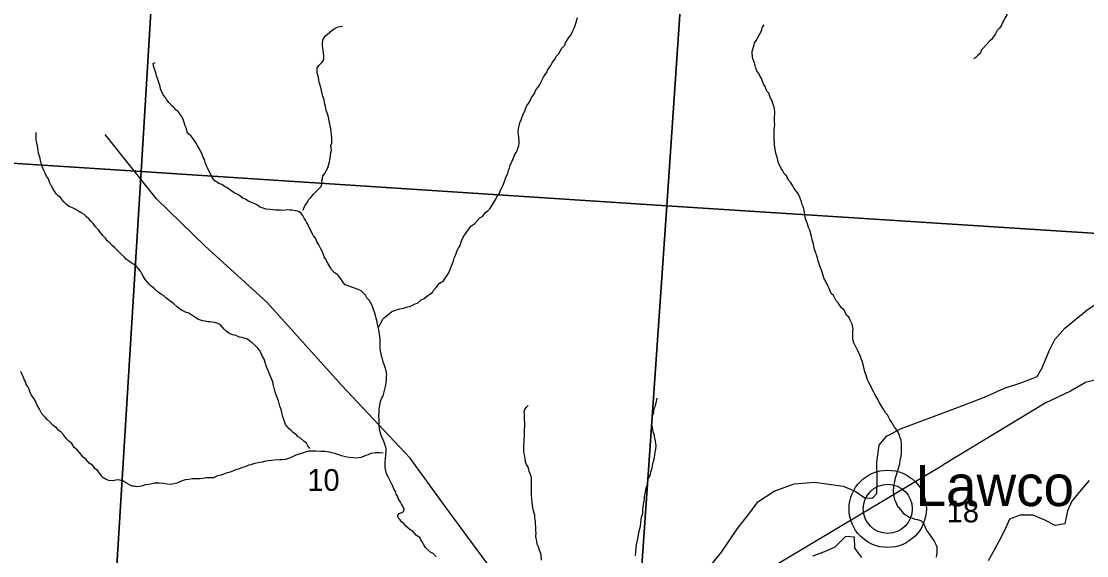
# Model space of a CAD drawing. Extents: x 0 to 44, y -23.8 to 22.
# Drawn here: x 5.27 to 7.321, y 17.815 to 18.843 of the extents above; entities that cross this region are included whole.
import ezdxf

# ---------------------------------------------------------------- set-up
doc = ezdxf.new("R2010")
doc.units = 0
for name, color, linetype in [('GM_X_County_Road', 7, 'Continuous'), ('GM_X_Minor_River', 7, 'Continuous'), ('GM_X_Rail_Line', 7, 'Continuous'), ('GM_X_Section', 7, 'Continuous'), ('GM_X_Section_Text', 7, 'Continuous'), ('GM_X_Township_Road', 7, 'Continuous'), ('GM_X_Unincorporated', 7, 'Continuous'), ('GM_X_Unincorporated_Location', 7, 'Continuous'), ('GM_X_Unincorporated_Text', 7, 'Continuous')]:
    doc.layers.add(name, color=color, linetype=linetype)

msp = doc.modelspace()

# ---------------------------------------------------------------- linework, layer by layer
at = {"layer": 'GM_X_County_Road'}
for points in [[(6.9605, 18.0572), (6.9631, 18.0586), (7.0676, 18.0977), (7.1245, 18.1197), (7.1631, 18.1368), (7.1965, 18.1482), (7.2162, 18.1554), (7.226, 18.1596), (7.2355, 18.1759), (7.2488, 18.2089), (7.2601, 18.2305), (7.2791, 18.2525), (7.3219, 18.2874), (7.3518, 18.3079), (7.3662, 18.3212), (7.3901, 18.3277), (7.4398, 18.3193), (7.4838, 18.3016), (7.5032, 18.2938)], [(6.5891, 17.785), (6.6186, 17.8214), (6.6489, 17.8669), (6.6728, 17.8969), (6.6883, 17.9182), (6.7198, 17.939), (6.7584, 17.9527), (6.7975, 17.9565), (6.8524, 17.9482), (6.8755, 17.9387), (6.8941, 17.9258), (6.9093, 17.9254), (6.9172, 17.9341), (6.918, 17.9614), (6.9172, 17.9948), (6.9218, 18.0275), (6.9362, 18.0445), (6.9474, 18.0504), (6.9605, 18.0572)]]:
    msp.add_lwpolyline(points, dxfattribs=at)
at = {"layer": 'GM_X_Minor_River'}
for points in [[(6.3108, 18.7915), (6.3169, 18.7971), (6.3181, 18.8017), (6.3243, 18.8115), (6.3285, 18.816), (6.3324, 18.8247), (6.3347, 18.8296), (6.3367, 18.8349), (6.3382, 18.839), (6.3414, 18.85)], [(7.1697, 18.8616), (7.1674, 18.8552), (7.1635, 18.8491), (7.1616, 18.8453), (7.1569, 18.8344), (7.1534, 18.8299), (7.1492, 18.825), (7.1457, 18.8186), (7.1388, 18.8088), (7.1334, 18.8039), (7.1288, 18.7983), (7.1226, 18.7919), (7.1184, 18.7874), (7.1172, 18.7813), (7.1118, 18.7768), (7.108, 18.7734), (7.1042, 18.7705)], [(5.8128, 18.4795), (5.8144, 18.4836), (5.8163, 18.4878), (5.8198, 18.4927), (5.8241, 18.4998), (5.8279, 18.5036), (5.8337, 18.5107), (5.8379, 18.5156), (5.8471, 18.5246), (5.8487, 18.5288), (5.8495, 18.5326), (5.8488, 18.5364), (5.85, 18.5401), (5.8512, 18.5458), (5.8546, 18.5503), (5.857, 18.5553), (5.8604, 18.5609), (5.8636, 18.5723), (5.8644, 18.5764), (5.8656, 18.5848), (5.8661, 18.5905), (5.8673, 18.5943), (5.8666, 18.6041), (5.8682, 18.6087), (5.8682, 18.6132), (5.8679, 18.6174), (5.8676, 18.6243), (5.8669, 18.63), (5.8662, 18.6361), (5.8648, 18.6418), (5.8644, 18.6456), (5.863, 18.6502), (5.8623, 18.6555), (5.8612, 18.6612), (5.8597, 18.665), (5.8575, 18.6711), (5.8568, 18.6749), (5.8561, 18.6799), (5.8546, 18.6837), (5.8532, 18.6913), (5.851, 18.699), (5.8492, 18.7062), (5.8474, 18.7127), (5.8463, 18.7173), (5.8452, 18.7218), (5.8441, 18.7256), (5.8434, 18.7298), (5.8423, 18.7352), (5.8412, 18.739), (5.8402, 18.7439), (5.8398, 18.7477), (5.8399, 18.7531), (5.8434, 18.7576), (5.8487, 18.7636), (5.8522, 18.7677), (5.8526, 18.7719), (5.8527, 18.7757), (5.8524, 18.7821), (5.8513, 18.7871), (5.8506, 18.7913), (5.8503, 18.7962), (5.8503, 18.8004), (5.8511, 18.8069), (5.8527, 18.811), (5.8558, 18.8148), (5.8596, 18.8182), (5.868, 18.8249), (5.8745, 18.8297), (5.8806, 18.8323), (5.8844, 18.833), (5.889, 18.8337)], [(6.8237, 18.3329), (6.8193, 18.3424), (6.8159, 18.3474), (6.8119, 18.36), (6.8071, 18.3745), (6.8042, 18.3814), (6.8038, 18.3852), (6.8013, 18.3939), (6.799, 18.3989), (6.7969, 18.4065), (6.7954, 18.4138), (6.7925, 18.4252), (6.7914, 18.429), (6.7885, 18.4408), (6.7859, 18.4462), (6.7834, 18.455), (6.7815, 18.4592), (6.7797, 18.4656), (6.7783, 18.4752), (6.7772, 18.4797), (6.7761, 18.4847), (6.7739, 18.4904), (6.7725, 18.4958), (6.7695, 18.5026), (6.7666, 18.5106), (6.7621, 18.516), (6.7583, 18.521), (6.7558, 18.5264), (6.7513, 18.5336), (6.7472, 18.5375), (6.7435, 18.5455), (6.7397, 18.549), (6.7364, 18.5555), (6.7334, 18.5597), (6.7308, 18.5654), (6.7282, 18.57), (6.7253, 18.5818), (6.7234, 18.5868), (6.7213, 18.6001), (6.7202, 18.6058), (6.72, 18.6195), (6.7197, 18.6252), (6.7198, 18.6332), (6.7203, 18.6393), (6.7207, 18.6442), (6.7204, 18.6492), (6.7204, 18.653), (6.7205, 18.6583), (6.7209, 18.6651), (6.721, 18.6693), (6.7196, 18.678), (6.7181, 18.6826), (6.7155, 18.6914), (6.7129, 18.6952), (6.7092, 18.7048), (6.7059, 18.7086), (6.7022, 18.7174), (6.6992, 18.722), (6.6955, 18.7327), (6.6929, 18.7365), (6.69, 18.7423), (6.6866, 18.7476), (6.6844, 18.753), (6.6818, 18.7629), (6.6789, 18.7709), (6.6782, 18.7755), (6.6775, 18.7808), (6.6772, 18.785), (6.6791, 18.7918), (6.6811, 18.7971), (6.6819, 18.8016), (6.685, 18.8062), (6.6881, 18.8118), (6.692, 18.8186), (6.6947, 18.8235), (6.6974, 18.8315), (6.7005, 18.836)], [(5.959, 18.2549), (5.9609, 18.2591), (5.9632, 18.2636), (5.9656, 18.2693), (5.9694, 18.2727), (5.9752, 18.2775), (5.979, 18.2809), (5.9836, 18.2846), (5.9874, 18.2861), (5.9946, 18.2883), (5.9988, 18.2898), (6.0068, 18.2912), (6.0114, 18.293), (6.0175, 18.2941), (6.0224, 18.2963), (6.0289, 18.2993), (6.0331, 18.3004), (6.0404, 18.3067), (6.0461, 18.3093), (6.0534, 18.3161), (6.0576, 18.3179), (6.0625, 18.3224), (6.0645, 18.3262), (6.0691, 18.3307), (6.0756, 18.3389), (6.0829, 18.3438), (6.0898, 18.3532), (6.0941, 18.36), (6.0976, 18.3691), (6.1004, 18.377), (6.1023, 18.3819), (6.1039, 18.3872), (6.1058, 18.391), (6.1074, 18.3963), (6.109, 18.4005), (6.1129, 18.4076), (6.1152, 18.4118), (6.1167, 18.4167), (6.1176, 18.4205), (6.1222, 18.4303), (6.1257, 18.4341), (6.1284, 18.4378), (6.1322, 18.4431), (6.1361, 18.4487), (6.1437, 18.454), (6.153, 18.4645), (6.1587, 18.4678), (6.1641, 18.475), (6.1687, 18.4783), (6.1737, 18.484), (6.1791, 18.4923), (6.1826, 18.4987), (6.1872, 18.5074), (6.1903, 18.5111), (6.1934, 18.5194), (6.1958, 18.5236), (6.1989, 18.5296), (6.2012, 18.5364), (6.2032, 18.5429), (6.2055, 18.5478), (6.2075, 18.5527), (6.2083, 18.5565), (6.2102, 18.5603), (6.2114, 18.5652), (6.2141, 18.5712), (6.2165, 18.5769), (6.2196, 18.5852), (6.2231, 18.5905), (6.225, 18.5943), (6.2262, 18.5984), (6.2282, 18.6037), (6.229, 18.6079), (6.229, 18.6121), (6.2284, 18.6197), (6.2273, 18.6258), (6.2269, 18.6296), (6.2274, 18.6368), (6.2302, 18.6478), (6.2329, 18.6534), (6.2365, 18.664), (6.2392, 18.6689), (6.2431, 18.6795), (6.2469, 18.6848), (6.2497, 18.6901), (6.2528, 18.6965), (6.2582, 18.704), (6.2609, 18.7108), (6.2655, 18.7161), (6.2678, 18.7203), (6.2729, 18.7301), (6.2756, 18.7357), (6.2787, 18.7406), (6.2818, 18.7444), (6.2833, 18.7486), (6.2868, 18.7531), (6.2895, 18.7576), (6.293, 18.7644), (6.2968, 18.7685), (6.3007, 18.7757), (6.3046, 18.7794), (6.3108, 18.7915)], [(5.8391, 18.4191), (5.8369, 18.4256), (5.8328, 18.4302), (5.8313, 18.434), (5.8287, 18.4382), (5.8264, 18.4428), (5.8238, 18.4474), (5.8224, 18.4516), (5.8201, 18.4554), (5.8175, 18.4604), (5.8149, 18.4642), (5.8127, 18.4692), (5.8093, 18.473), (5.8056, 18.4761), (5.8018, 18.4777), (5.7976, 18.4785), (5.7916, 18.4793), (5.7874, 18.4794), (5.781, 18.4799), (5.7753, 18.4792), (5.7696, 18.4796), (5.7654, 18.4797), (5.7597, 18.4797), (5.7495, 18.4806), (5.7415, 18.4815), (5.734, 18.4843), (5.7298, 18.4854), (5.7253, 18.4889), (5.72, 18.492), (5.7136, 18.4944), (5.7064, 18.4975), (5.7019, 18.5006), (5.6978, 18.5022), (5.6887, 18.5091), (5.6801, 18.5131), (5.6755, 18.5162), (5.6658, 18.5231), (5.6616, 18.5251), (5.6563, 18.5286), (5.6518, 18.5301), (5.6469, 18.5332), (5.6431, 18.5359), (5.6379, 18.5425), (5.6357, 18.5463), (5.6342, 18.5505), (5.6312, 18.5555), (5.6294, 18.5597), (5.6272, 18.5646), (5.6253, 18.5692), (5.6228, 18.5769), (5.6205, 18.5811), (5.619, 18.5849), (5.618, 18.5887), (5.6153, 18.5929), (5.6135, 18.5975), (5.6098, 18.6036), (5.6068, 18.6082), (5.6035, 18.6143), (5.5971, 18.6216), (5.593, 18.6259), (5.59, 18.6297), (5.5889, 18.6335), (5.5878, 18.6377), (5.5859, 18.6419), (5.5841, 18.6484), (5.5827, 18.6522), (5.5812, 18.656), (5.5789, 18.6602), (5.5748, 18.6652), (5.5722, 18.6694), (5.5685, 18.6718), (5.5643, 18.6768), (5.5606, 18.6795), (5.5546, 18.6868), (5.5497, 18.6922), (5.5479, 18.696), (5.5438, 18.7013), (5.5408, 18.7075), (5.5386, 18.7128), (5.5375, 18.7174), (5.5353, 18.725), (5.5324, 18.7326), (5.5309, 18.738), (5.5295, 18.7437), (5.5284, 18.7479), (5.5258, 18.7548), (5.5243, 18.7616), (5.5282, 18.7635)], [(5.3618, 18.4867), (5.3566, 18.491), (5.3517, 18.4963), (5.3457, 18.5036), (5.3416, 18.5071), (5.3378, 18.511), (5.3341, 18.5163), (5.3311, 18.5209), (5.3285, 18.5255), (5.3248, 18.5335), (5.3226, 18.5396), (5.3189, 18.545), (5.3167, 18.5492), (5.3141, 18.5557), (5.3108, 18.5637), (5.3093, 18.5679), (5.3071, 18.5744), (5.3068, 18.5797), (5.3057, 18.5836), (5.3038, 18.5893), (5.3028, 18.5946), (5.3024, 18.5996), (5.3017, 18.6041), (5.3006, 18.6079), (5.2992, 18.6152), (5.2989, 18.6201), (5.299, 18.6289)], [(5.8258, 18.0211), (5.822, 18.0264), (5.8194, 18.0314), (5.8142, 18.0353), (5.8078, 18.0407), (5.8033, 18.0434), (5.7995, 18.0476), (5.7942, 18.0511), (5.7897, 18.0557), (5.7856, 18.0592), (5.7792, 18.0673), (5.7763, 18.0749), (5.7737, 18.0821), (5.7705, 18.0962), (5.7679, 18.1024), (5.7654, 18.1126), (5.7628, 18.1188), (5.7595, 18.1283), (5.7576, 18.1348), (5.7558, 18.142), (5.7548, 18.1493), (5.7529, 18.1535), (5.7511, 18.1584), (5.7489, 18.163), (5.7459, 18.171), (5.7426, 18.1783), (5.7382, 18.1928), (5.7334, 18.2004), (5.7297, 18.2096), (5.7252, 18.2146), (5.7211, 18.2188), (5.7143, 18.2246), (5.7102, 18.2277), (5.706, 18.2312), (5.6992, 18.2332), (5.6951, 18.2344), (5.6905, 18.2352), (5.6818, 18.2387), (5.6773, 18.2399), (5.6697, 18.2427), (5.6648, 18.2469), (5.6611, 18.2504), (5.654, 18.2588), (5.6487, 18.2615), (5.6423, 18.2632), (5.6377, 18.264), (5.6332, 18.2644), (5.6294, 18.2648), (5.6241, 18.2657), (5.6192, 18.2665), (5.6154, 18.2681), (5.6116, 18.2689), (5.6067, 18.2723), (5.5984, 18.2778), (5.5928, 18.2813), (5.5864, 18.2832), (5.5803, 18.2867), (5.5747, 18.2895), (5.5709, 18.2926), (5.5638, 18.2991), (5.5563, 18.3049), (5.5487, 18.3107), (5.5442, 18.3153), (5.5386, 18.3188), (5.5337, 18.3215), (5.5262, 18.3288), (5.5202, 18.3331), (5.5164, 18.3369), (5.5134, 18.3412), (5.5086, 18.3462), (5.5048, 18.3523), (5.5015, 18.3584), (5.4996, 18.3622), (5.4959, 18.3668), (5.4914, 18.3715), (5.4876, 18.3749), (5.482, 18.378), (5.4767, 18.3823), (5.473, 18.3846), (5.4685, 18.3896), (5.4625, 18.395), (5.4542, 18.4035), (5.4505, 18.4069), (5.4452, 18.4116), (5.4396, 18.4181), (5.4358, 18.4204), (5.4325, 18.4254), (5.4272, 18.4308), (5.4216, 18.4377), (5.419, 18.4419), (5.4134, 18.4477), (5.4093, 18.4531), (5.4044, 18.4584), (5.4003, 18.463), (5.3961, 18.4665), (5.3916, 18.4715), (5.3871, 18.4735), (5.3792, 18.4781), (5.3754, 18.4805), (5.3675, 18.4844), (5.3618, 18.4867)], [(5.9957, 17.8874), (5.995, 17.892), (5.9981, 17.8962), (6.003, 17.898), (6.0068, 17.9006), (6.0073, 17.9044), (6.0054, 17.909), (6.0024, 17.9136), (5.9995, 17.9193), (5.9961, 17.9247), (5.9947, 17.9293), (5.992, 17.9331), (5.9906, 17.938), (5.9876, 17.9434), (5.9858, 17.9484), (5.9828, 17.9533), (5.9813, 17.9575), (5.9783, 17.9625), (5.9769, 17.9667), (5.9739, 17.9709), (5.9728, 17.9747), (5.971, 17.9843), (5.9711, 17.9953), (5.9716, 18.0006), (5.9721, 18.0097), (5.9725, 18.0143), (5.9726, 18.0207), (5.9715, 18.0249), (5.9697, 18.0314), (5.9671, 18.0379), (5.9637, 18.0448), (5.9623, 18.0486), (5.9604, 18.0555), (5.9601, 18.06), (5.9594, 18.0653), (5.9591, 18.0703), (5.9592, 18.0764), (5.9589, 18.0836), (5.9593, 18.0916), (5.9594, 18.0961), (5.9598, 18.1011), (5.961, 18.1075), (5.9622, 18.1117), (5.9646, 18.1185), (5.9669, 18.1222), (5.9681, 18.1272), (5.9697, 18.1325), (5.9709, 18.1374), (5.9721, 18.1427), (5.9729, 18.148), (5.9733, 18.1537), (5.9734, 18.1594), (5.9738, 18.1636), (5.9735, 18.1674), (5.9724, 18.1731), (5.9691, 18.1826), (5.9673, 18.1868), (5.9655, 18.1937), (5.9636, 18.1983), (5.9629, 18.2028), (5.9618, 18.2086), (5.9615, 18.2143), (5.9612, 18.2207), (5.9613, 18.2283), (5.961, 18.2325), (5.9606, 18.2363), (5.9596, 18.2454), (5.9582, 18.2527), (5.9567, 18.2572), (5.9549, 18.2675), (5.9535, 18.2717), (5.9524, 18.2767), (5.9509, 18.2816), (5.9487, 18.2881), (5.9469, 18.2923), (5.945, 18.2977), (5.9424, 18.3019), (5.9402, 18.3061), (5.9353, 18.3111), (5.9331, 18.3157), (5.9252, 18.3238), (5.9211, 18.3261), (5.9139, 18.3285), (5.9082, 18.3308), (5.903, 18.3328), (5.898, 18.3344), (5.8939, 18.3359), (5.8898, 18.3406), (5.8857, 18.3471), (5.8801, 18.3544), (5.8729, 18.3594), (5.8673, 18.3655), (5.8651, 18.3701), (5.8613, 18.3762), (5.8561, 18.3862), (5.8535, 18.39), (5.8524, 18.3938), (5.8502, 18.3992), (5.8469, 18.4049), (5.8435, 18.4126), (5.8391, 18.4191)], [(7.032, 17.812), (7.0333, 17.8199), (7.0337, 17.8241), (7.0334, 17.831), (7.0316, 17.8359), (7.0293, 17.8405), (7.0271, 17.8447), (7.0237, 17.8489), (7.0189, 17.8566), (7.0144, 17.8627), (7.0118, 17.8673), (7.01, 17.8719), (7.007, 17.8773), (7.0025, 17.8815), (6.9957, 17.8835), (6.9911, 17.8843), (6.9851, 17.8867), (6.9813, 17.8878), (6.9757, 17.891), (6.9696, 17.8952), (6.967, 17.899), (6.9618, 17.9056), (6.9577, 17.909), (6.954, 17.9182), (6.9517, 17.922), (6.9504, 17.9331), (6.9496, 17.9376), (6.9502, 17.9487), (6.9522, 17.9577), (6.9534, 17.9646), (6.955, 17.9702), (6.9569, 17.9771), (6.9593, 17.9827), (6.9605, 17.9873), (6.9617, 17.9914), (6.9625, 17.9979), (6.9645, 18.0062), (6.9649, 18.0104), (6.9651, 18.029), (6.9641, 18.037), (6.9626, 18.0412), (6.9604, 18.0477), (6.9586, 18.0523), (6.9548, 18.0584), (6.9515, 18.0622), (6.9463, 18.071), (6.9429, 18.0753), (6.9377, 18.086), (6.9339, 18.0894), (6.931, 18.0956), (6.9254, 18.104), (6.9228, 18.1086), (6.9198, 18.1147), (6.9142, 18.1239), (6.9113, 18.1296), (6.9083, 18.135), (6.9061, 18.1407), (6.902, 18.148), (6.8994, 18.153), (6.8968, 18.1621), (6.895, 18.1663), (6.8928, 18.1735), (6.8914, 18.18), (6.8892, 18.1892), (6.8874, 18.1938), (6.8866, 18.1976), (6.8829, 18.2041), (6.8811, 18.2087), (6.8777, 18.2152), (6.8755, 18.2194), (6.8737, 18.2232), (6.8718, 18.2274), (6.8711, 18.2331), (6.8713, 18.2468), (6.8717, 18.2509), (6.8699, 18.2605), (6.8662, 18.2677), (6.8636, 18.2738), (6.8599, 18.2769), (6.8573, 18.2811), (6.8547, 18.2869), (6.8494, 18.2915), (6.8464, 18.2961), (6.8431, 18.3015), (6.8393, 18.3049), (6.8341, 18.3153), (6.8296, 18.3191), (6.8256, 18.329), (6.8237, 18.3329)], [(5.3676, 18.0307), (5.3619, 18.0353), (5.3571, 18.04), (5.3526, 18.0469), (5.347, 18.0522), (5.3425, 18.0557), (5.338, 18.0607), (5.3312, 18.0661), (5.3259, 18.0719), (5.3203, 18.0765), (5.3162, 18.0811), (5.3102, 18.0877), (5.3057, 18.0968), (5.3009, 18.1041), (5.2957, 18.1156), (5.2894, 18.1244), (5.2868, 18.1305), (5.2846, 18.1362), (5.2827, 18.1404), (5.2797, 18.1443), (5.279, 18.1485), (5.2768, 18.1527), (5.2738, 18.1592), (5.2716, 18.1645), (5.2694, 18.1691)], [(6.4531, 17.8144), (6.4536, 17.8227), (6.4549, 17.836), (6.4557, 17.8413), (6.4581, 17.8512), (6.4593, 17.8595), (6.4621, 17.8716), (6.4646, 17.8891), (6.4666, 17.8959), (6.467, 17.902), (6.4683, 17.9134), (6.4695, 17.9194), (6.4699, 17.9232), (6.47, 17.9289), (6.4712, 17.9335), (6.4736, 17.9452), (6.4752, 17.9497), (6.4756, 17.9535), (6.478, 17.9641), (6.4807, 17.969), (6.4827, 17.9778), (6.4851, 17.9834), (6.4855, 17.9884), (6.4883, 17.9993), (6.4895, 18.0039), (6.4907, 18.0141), (6.4919, 18.0194), (6.4924, 18.0263), (6.4921, 18.0308), (6.491, 18.0354), (6.4895, 18.0442), (6.4885, 18.0484), (6.487, 18.0533), (6.4859, 18.0579), (6.4852, 18.0617), (6.4845, 18.0659), (6.4842, 18.0708), (6.4851, 18.0826), (6.487, 18.0871), (6.4878, 18.0913), (6.489, 18.0977), (6.491, 18.103), (6.4922, 18.1076), (6.4934, 18.1117), (6.4946, 18.1178)], [(6.2721, 17.8064), (6.2714, 17.8159), (6.27, 17.8205), (6.2681, 17.8251), (6.2663, 17.8316), (6.2637, 17.8369), (6.2626, 17.8426), (6.2616, 17.8476), (6.2608, 17.8522), (6.2613, 17.8582), (6.2606, 17.8632), (6.2607, 17.8685), (6.2604, 17.8765), (6.26, 17.8818), (6.2593, 17.8868), (6.259, 17.8925), (6.2576, 17.8963), (6.2561, 17.9035), (6.255, 17.9077), (6.254, 17.9161), (6.2529, 17.9241), (6.2527, 17.9321), (6.2527, 17.9389), (6.2524, 17.945), (6.2526, 17.9602), (6.2523, 17.9647), (6.2508, 17.9708), (6.2482, 17.9769), (6.2472, 17.9808), (6.2453, 17.9861), (6.2431, 17.9899), (6.2409, 17.9953), (6.2402, 17.9995), (6.2395, 18.0063), (6.2381, 18.0139), (6.2381, 18.0204), (6.2378, 18.0242), (6.2378, 18.028), (6.2383, 18.0341), (6.2383, 18.039), (6.2388, 18.0462), (6.2393, 18.0519), (6.2395, 18.0705), (6.2392, 18.0777), (6.2389, 18.0831), (6.2389, 18.0872), (6.2382, 18.0918), (6.2398, 18.096), (6.2421, 18.1001), (6.2463, 18.1039)], [(5.9668, 18.0117), (5.96, 18.0125), (5.952, 18.0126), (5.9482, 18.0123), (5.9433, 18.0116), (5.9383, 18.009), (5.9337, 18.0072), (5.9291, 18.0057), (5.9242, 18.0035), (5.9166, 18.0024), (5.9098, 18.0029), (5.9022, 18.0038), (5.8969, 18.0046), (5.892, 18.0058), (5.887, 18.007), (5.8818, 18.009), (5.878, 18.0101), (5.8738, 18.0113), (5.8685, 18.0129), (5.864, 18.0137), (5.8545, 18.015), (5.8469, 18.0155), (5.8371, 18.0156), (5.8333, 18.016), (5.828, 18.0161), (5.8234, 18.0158), (5.8185, 18.0143), (5.8116, 18.0118), (5.8048, 18.0099), (5.7987, 18.0081), (5.7914, 18.004), (5.7827, 18.0011), (5.7788, 18), (5.7728, 17.9993), (5.769, 17.999), (5.7572, 17.9984), (5.7519, 17.9981), (5.7466, 17.997), (5.7412, 17.9963), (5.734, 17.9945), (5.7295, 17.9942), (5.7173, 17.9913), (5.712, 17.9898), (5.7082, 17.9888), (5.7005, 17.9858), (5.6944, 17.984), (5.6883, 17.981), (5.6845, 17.9803), (5.6746, 17.9763), (5.6701, 17.9748), (5.6647, 17.9733), (5.6586, 17.9711), (5.6548, 17.9697), (5.6484, 17.9682), (5.6403, 17.9645), (5.6358, 17.9646), (5.6271, 17.9643), (5.6206, 17.9633), (5.6149, 17.9626), (5.6092, 17.9623), (5.5997, 17.9624), (5.5929, 17.9613), (5.5861, 17.9607), (5.5803, 17.9588), (5.5754, 17.957), (5.57, 17.9544), (5.5643, 17.953), (5.5586, 17.9519), (5.5514, 17.9524), (5.5442, 17.9536), (5.5359, 17.9545), (5.5306, 17.9545), (5.526, 17.9542), (5.5219, 17.9531), (5.5158, 17.9517), (5.5093, 17.951), (5.5021, 17.9488), (5.4926, 17.947), (5.488, 17.9482), (5.4839, 17.9487), (5.4801, 17.9506), (5.4729, 17.9545), (5.4669, 17.958), (5.4601, 17.96), (5.4552, 17.9604), (5.4498, 17.9597), (5.4453, 17.959), (5.4388, 17.9591), (5.4335, 17.9611), (5.426, 17.9661), (5.4234, 17.97), (5.4174, 17.9784), (5.4122, 17.9826), (5.4073, 17.9888), (5.4009, 17.9927), (5.3953, 18), (5.3893, 18.0042), (5.3826, 18.013), (5.3777, 18.0184), (5.3724, 18.023), (5.3676, 18.0307)], [(7.3263, 17.9595), (7.311, 17.9413), (7.2926, 17.9194), (7.2842, 17.9012), (7.2791, 17.8762), (7.2608, 17.8725), (7.2393, 17.884), (7.2181, 17.8928), (7.1935, 17.8929), (7.1729, 17.8847), (7.1645, 17.8657), (7.1537, 17.8445), (7.1437, 17.8267), (7.1314, 17.8048)], [(6.0688, 17.8128), (6.0636, 17.819), (6.059, 17.8209), (6.0527, 17.8263), (6.0485, 17.8305), (6.0452, 17.8355), (6.0426, 17.8409), (6.0396, 17.8451), (6.0374, 17.8497), (6.0313, 17.8536), (6.0265, 17.8586), (6.0235, 17.8624), (6.0193, 17.8643), (6.0148, 17.8682), (6.0107, 17.8717), (6.0069, 17.8767), (6.0024, 17.8798), (5.9998, 17.8836), (5.9957, 17.8874)], [(6.8884, 17.811), (6.8752, 17.8289), (6.8742, 17.8505), (6.8572, 17.8518), (6.8362, 17.8314), (6.8168, 17.822), (6.7936, 17.8137)]]:
    msp.add_lwpolyline(points, dxfattribs=at)
at = {"layer": 'GM_X_Rail_Line'}
msp.add_lwpolyline([(7.3576, 18.1574), (7.3191, 18.1482), (7.2902, 18.1314), (7.2413, 18.1084), (7.0462, 17.99), (7.045, 17.9889), (6.5222, 17.6767)], dxfattribs=at)
at = {"layer": 'GM_X_Section'}
for points in [[(4.5363, 19.6324), (5.5628, 19.5693), (5.5009, 18.5537), (4.4853, 18.6191)], [(5.5628, 19.5693), (6.5821, 19.5069), (6.5134, 18.488), (5.5009, 18.5537)], [(6.5821, 19.5069), (7.5875, 19.4351), (7.5123, 18.4238), (6.5134, 18.488)], [(4.4853, 18.6191), (5.5009, 18.5537), (5.4377, 17.5257), (4.437, 17.5902)], [(5.5009, 18.5537), (6.5134, 18.488), (6.4419, 17.4633), (5.4377, 17.5257)], [(6.5134, 18.488), (7.5123, 18.4238), (7.4446, 17.3999), (6.4419, 17.4633)]]:
    msp.add_lwpolyline(points, close=True, dxfattribs=at)
at = {"layer": 'GM_X_Township_Road'}
msp.add_lwpolyline([(6.2073, 17.7179), (6.1995, 17.7431), (6.1861, 17.7744), (6.085, 17.9112), (6.0188, 18.0021), (5.8865, 18.1427), (5.7431, 18.3026), (5.6246, 18.4101), (5.5308, 18.5011), (5.4316, 18.6252)], dxfattribs=at)
at = {"layer": 'GM_X_Unincorporated'}
for radius in [0.0744, 0.0472]:
    msp.add_circle((6.9383, 17.9049), radius, dxfattribs=at)
at = {"layer": 'GM_X_Unincorporated_Location'}
msp.add_line((6.9383, 17.9049), (6.9383, 17.9049), dxfattribs=at)

# ---------------------------------------------------------------- texts
at = {"layer": 'GM_X_Section_Text'}
for s, p in [('10', (5.821, 17.9394)), ('18', (7.0518, 17.8789))]:
    msp.add_text(s, height=0.04186, rotation=0, dxfattribs=at).set_placement(p)
at = {"layer": 'GM_X_Unincorporated_Text'}
msp.add_text('Lawco', height=0.07898, rotation=0, dxfattribs=at).set_placement((6.9918, 17.9101))

doc.saveas('drawing.dxf')
